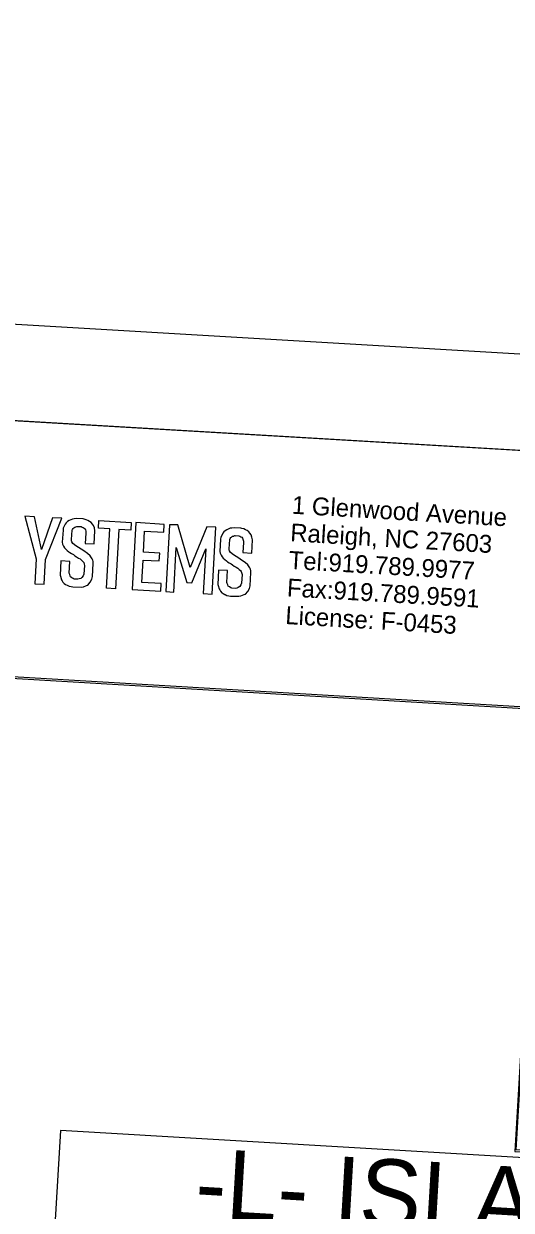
# Model space of a CAD drawing. Extents: x 2011491 to 2012372, y 444688 to 445287.
# Drawn here: x 2012189.4 to 2012252.9, y 445132.9 to 445287.5 of the extents above; entities that cross this region are included whole.
import ezdxf

# ---------------------------------------------------------------- set-up
doc = ezdxf.new("R2010")
doc.units = 0
for name, color, linetype in [('Old_Level_1', 7, 'Continuous'), ('Old_Level_2', 7, 'Continuous'), ('Old_Level_58', 7, 'Continuous'), ('Prop Dimension', 7, 'Continuous'), ('Sheet Clip Boundary CELL', 7, 'Continuous'), ('Sheet Plan And Profile CELL', 7, 'Continuous'), ('Sheet Plot Border Outside CELL', 7, 'Continuous')]:
    doc.layers.add(name, color=color, linetype=linetype)

msp = doc.modelspace()

# ---------------------------------------------------------------- linework, layer by layer
at = {"layer": 'Old_Level_1'}
for points in [[(2012190.78, 445223.21), (2012189.51, 445223.29), (2012191, 445217.75), (2012190.82, 445214.48), (2012192.01, 445214.42), (2012192.19, 445217.66), (2012194.34, 445223.02), (2012193.09, 445223.06), (2012191.69, 445218.97)], [(2012197.38, 445219.73), (2012198.54, 445219.67), (2012198.64, 445221.4), (2012198.56, 445221.76), (2012198.44, 445222.06), (2012198.3, 445222.27), (2012198.13, 445222.45), (2012197.92, 445222.61), (2012197.71, 445222.71), (2012197.71, 445222.71), (2012197.49, 445222.82), (2012197.25, 445222.89), (2012197.09, 445222.94), (2012196.22, 445222.98), (2012195.95, 445222.95), (2012195.72, 445222.92), (2012195.48, 445222.81), (2012195.27, 445222.72), (2012195.07, 445222.59), (2012194.9, 445222.44), (2012194.77, 445222.27), (2012194.66, 445222.08), (2012194.52, 445221.74), (2012194.48, 445221.48), (2012194.38, 445219.9), (2012194.43, 445219.66), (2012194.53, 445219.4), (2012194.66, 445219.19), (2012194.8, 445219.03), (2012195.01, 445218.84), (2012195.23, 445218.65), (2012195.36, 445218.54), (2012195.6, 445218.41), (2012195.83, 445218.28), (2012196.02, 445218.14), (2012196.23, 445217.99), (2012196.49, 445217.84), (2012196.7, 445217.72), (2012196.9, 445217.55), (2012197.05, 445217.39), (2012197.17, 445217.27), (2012197.23, 445217.02), (2012197.27, 445216.87), (2012197.18, 445215.75), (2012197.09, 445215.52), (2012196.95, 445215.31), (2012196.78, 445215.18), (2012196.6, 445215.11), (2012196.43, 445215.08), (2012195.95, 445215.1), (2012195.79, 445215.16), (2012195.63, 445215.26), (2012195.47, 445215.37), (2012195.41, 445215.54), (2012195.35, 445215.71), (2012195.3, 445215.85), (2012195.37, 445217.4), (2012194.21, 445217.46), (2012194.12, 445215.6), (2012194.17, 445215.46), (2012194.28, 445215.02), (2012194.36, 445214.87), (2012194.47, 445214.7), (2012194.65, 445214.51), (2012194.8, 445214.4), (2012195.01, 445214.3), (2012195.09, 445214.26), (2012195.3, 445214.16), (2012195.56, 445214.11), (2012195.76, 445214.08), (2012196.83, 445214.05), (2012197.13, 445214.1), (2012197.55, 445214.26), (2012197.7, 445214.32), (2012198.03, 445214.69), (2012198.22, 445215.08), (2012198.32, 445215.43), (2012198.39, 445217.14), (2012198.4, 445217.37), (2012198.35, 445217.56), (2012198.26, 445217.75), (2012198.02, 445218.14), (2012197.68, 445218.44), (2012197.21, 445218.76), (2012196.85, 445219), (2012196.14, 445219.43), (2012195.78, 445219.73), (2012195.63, 445219.95), (2012195.6, 445220.09), (2012195.57, 445220.24), (2012195.66, 445221.45), (2012195.73, 445221.57), (2012195.8, 445221.7), (2012195.9, 445221.77), (2012196.02, 445221.86), (2012196.15, 445221.9), (2012196.28, 445221.95), (2012196.36, 445221.93), (2012196.36, 445221.97), (2012196.84, 445221.93), (2012196.98, 445221.87), (2012197.11, 445221.81), (2012197.25, 445221.74), (2012197.31, 445221.64), (2012197.39, 445221.5), (2012197.43, 445221.36), (2012197.47, 445221.22), (2012197.45, 445221.07)], [(2012199.14, 445222.73), (2012203.37, 445222.49), (2012203.31, 445221.45), (2012201.76, 445221.54), (2012201.31, 445213.84), (2012200.14, 445213.91), (2012200.59, 445221.66), (2012199.1, 445221.75)], [(2012207.66, 445222.23), (2012203.98, 445222.45), (2012203.47, 445213.75), (2012207.2, 445213.53), (2012207.26, 445214.51), (2012204.74, 445214.66), (2012204.91, 445217.58), (2012207.01, 445217.46), (2012207.07, 445218.49), (2012204.95, 445218.61), (2012205.11, 445221.36), (2012207.61, 445221.21)], [(2012211.03, 445216.6), (2012209.45, 445222.16), (2012208.34, 445222.18), (2012207.87, 445213.46), (2012208.92, 445213.4), (2012209.23, 445219.23), (2012210.6, 445214.65), (2012211.27, 445214.59), (2012213.07, 445219.06), (2012212.75, 445213.21), (2012213.89, 445213.15), (2012214.37, 445221.84), (2012213.22, 445221.91)], [(2012217.92, 445218.54), (2012219.07, 445218.48), (2012219.17, 445220.21), (2012219.09, 445220.57), (2012218.97, 445220.87), (2012218.83, 445221.08), (2012218.66, 445221.26), (2012218.45, 445221.42), (2012218.24, 445221.52), (2012218.24, 445221.52), (2012218.02, 445221.63), (2012217.78, 445221.7), (2012217.62, 445221.75), (2012216.75, 445221.78), (2012216.48, 445221.75), (2012216.25, 445221.73), (2012216.01, 445221.62), (2012215.81, 445221.53), (2012215.6, 445221.4), (2012215.44, 445221.25), (2012215.3, 445221.08), (2012215.2, 445220.88), (2012215.05, 445220.54), (2012215.01, 445220.29), (2012214.92, 445218.71), (2012214.96, 445218.47), (2012215.06, 445218.21), (2012215.19, 445218), (2012215.33, 445217.84), (2012215.54, 445217.65), (2012215.76, 445217.46), (2012215.9, 445217.34), (2012216.13, 445217.22), (2012216.36, 445217.09), (2012216.55, 445216.95), (2012216.76, 445216.8), (2012217.02, 445216.65), (2012217.23, 445216.53), (2012217.43, 445216.36), (2012217.58, 445216.2), (2012217.7, 445216.07), (2012217.76, 445215.83), (2012217.8, 445215.68), (2012217.71, 445214.56), (2012217.62, 445214.33), (2012217.49, 445214.12), (2012217.31, 445213.99), (2012217.13, 445213.92), (2012216.96, 445213.89), (2012216.48, 445213.91), (2012216.32, 445213.96), (2012216.16, 445214.07), (2012216, 445214.18), (2012215.94, 445214.35), (2012215.88, 445214.52), (2012215.83, 445214.66), (2012215.91, 445216.21), (2012214.74, 445216.27), (2012214.65, 445214.41), (2012214.7, 445214.27), (2012214.81, 445213.83), (2012214.89, 445213.68), (2012215.01, 445213.51), (2012215.18, 445213.31), (2012215.33, 445213.21), (2012215.54, 445213.11), (2012215.62, 445213.07), (2012215.83, 445212.96), (2012216.09, 445212.92), (2012216.29, 445212.89), (2012217.36, 445212.86), (2012217.66, 445212.91), (2012218.08, 445213.07), (2012218.23, 445213.13), (2012218.56, 445213.5), (2012218.75, 445213.89), (2012218.85, 445214.23), (2012218.92, 445215.94), (2012218.93, 445216.18), (2012218.88, 445216.37), (2012218.79, 445216.55), (2012218.55, 445216.95), (2012218.21, 445217.25), (2012217.74, 445217.57), (2012217.38, 445217.81), (2012216.67, 445218.24), (2012216.31, 445218.54), (2012216.16, 445218.76), (2012216.13, 445218.9), (2012216.1, 445219.05), (2012216.2, 445220.26), (2012216.27, 445220.38), (2012216.33, 445220.5), (2012216.43, 445220.58), (2012216.55, 445220.67), (2012216.68, 445220.71), (2012216.81, 445220.76), (2012216.89, 445220.74), (2012216.9, 445220.78), (2012217.37, 445220.74), (2012217.51, 445220.68), (2012217.64, 445220.61), (2012217.78, 445220.55), (2012217.84, 445220.45), (2012217.92, 445220.31), (2012217.96, 445220.17), (2012218, 445220.03), (2012217.99, 445219.87)], [(2012193.42, 445130.88), (2012339.99, 445122.24), (2012340.72, 445134.62), (2012194.15, 445143.26)]]:
    msp.add_lwpolyline(points, close=True, dxfattribs=at)
at = {"layer": 'Old_Level_58'}
msp.add_lwpolyline([(2012159.02, 445237.47), (2012258.87, 445231.58), (2012256.91, 445198.29), (2012157.05, 445204.18)], close=True, dxfattribs=at)
at = {"layer": 'Sheet Clip Boundary CELL'}
for points in [[(2012353.36, 445134.84), (2012253.51, 445140.73), (2012256.91, 445198.29), (2012157.05, 445204.18), (2012159.02, 445237.47), (2011610.02, 445269.83), (2011579.13, 444745.74), (2012327.83, 444701.6)], [(2011579.79, 444746.22), (2011610.64, 445269.52), (2012158.83, 445237.2), (2012156.87, 445204), (2012256.73, 445198.11), (2012253.34, 445140.51), (2012353.28, 445134.62), (2012327.76, 444701.71)]]:
    msp.add_lwpolyline(points, close=True, dxfattribs=at)
at = {"layer": 'Sheet Plan And Profile CELL'}
msp.add_lwpolyline([(2012358.72, 445225.69), (2011610.02, 445269.83), (2011579.13, 444745.74), (2012327.83, 444701.6)], close=True, dxfattribs=at)
at = {"layer": 'Sheet Plot Border Outside CELL'}
msp.add_lwpolyline([(2011491.04, 444738.41), (2012339.57, 444688.39), (2012371.93, 445237.44), (2011523.41, 445287.46)], close=True, dxfattribs=at)

# ---------------------------------------------------------------- texts
at = {"layer": 'Old_Level_2'}
for s, p in [('1 Glenwood Avenue', (2012224.24, 445223.62)), ('Raleigh, NC 27603', (2012224.03, 445220.03)), ('Tel:919.789.9977 ', (2012223.82, 445216.44)), ('Fax:919.789.9591', (2012223.6, 445212.85)), ('License: F-0453', (2012223.39, 445209.25))]:
    msp.add_text(s, height=2.3288, rotation=356.6264, dxfattribs=at).set_placement(p)
at = {"layer": 'Prop Dimension'}
msp.add_text('-L- ISLAND DETAIL', height=9, rotation=356.6264, dxfattribs=at).set_placement((2012211.53, 445131.99))

doc.saveas('drawing.dxf')
